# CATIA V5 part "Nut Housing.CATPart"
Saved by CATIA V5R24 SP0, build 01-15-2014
Part number: Nut Housing
Bounding box of the stored display mesh (mm): x -15 to 15, y -30 to 30, z -10 to 10
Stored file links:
  C:\Users\minsi\Google 드라이브\CDL_2019\00_CLASS\00_CAD\기말고사\DMU\Nut Housing.CATPart
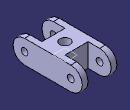
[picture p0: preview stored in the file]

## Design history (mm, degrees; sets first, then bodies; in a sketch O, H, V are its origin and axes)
Body1 (main body)
  Sketch1 on yz-plane, origin (0, 0, 0), H (0, 1, 0), V (0, 0, 1)
    construction line L1 (-20, 0) -> (20, 0)
    point P1 (-20, 0)
    line L2 (-20, 10) -> (20, 10)
    line L3 (20, -10) -> (-20, -10)
    arc A1 centre (20, 0) radius 10 from (20, 10) to (20, -10) cw
    arc A2 centre (-20, 0) radius 10 from (-20, -10) to (-20, 10) cw
    distance L1 L2 = 10
    length L1 = 40
    distance P1 V = 20
    horizontal: L1 H
    tangency: A1 L2, A2 L2, A1 L3, A2 L3
    coincidence: L1 H
  Pad1: profile Sketch1, direction (1, 0, 0), length 15, mirrored extent
  Sketch2 on end face of Pad1, origin (15, 22.454, 0), H (0, 1, 0), V (0, 0, 1)
    point P1 (-2.454, 0)
    reference projected arc E1 centre (-2.454, 0) radius 10 from (-2.454, -10) to (-2.454, 10) ccw from edge [face of Pad1 from Sketch1.A1 | end face of Pad1]
    concentricity: E1 P1
  Hole1: placed by Sketch2, at (15, 20, 0) direction (-1, 0, 0), diameter 6, through (limit type 3)
  Sketch3 on end face of Pad1, origin (15, -24.4239, 1.7761), H (0, 1, 0), V (0, 0, 1)
    point P1 (4.4239, -1.7761)
    reference projected arc E1 centre (4.4239, -1.7761) radius 10 from (4.4239, 8.2239) to (4.4239, -11.7761) ccw from edge [face of Pad1 from Sketch1.A2 | end face of Pad1]
    concentricity: E1 P1
  Hole2: placed by Sketch3, at (15, -20, 0) direction (-1, 0, 0), diameter 6, through (limit type 3)
  Sketch4 on face of Pad1 from Sketch1.L2, origin (-7.6845, 2.0131, 10), H (1, 0, 0), V (0, 1, 0)
    point P1 (7.6845, -2.0131)
    reference intersected line E1 through (0, -2.0131) direction (-1, 0) from zx-plane
    reference intersected line E2 through (7.6845, 0) direction (0, 1) from yz-plane
    coincidence: P1 E1, P1 E2
  Hole3: placed by Sketch4, at (0, 0, 10) direction (0, 0, -1), diameter 9, through (limit type 3)
  Sketch5 on xy-plane, origin (0, 0, 0), H (1, 0, 0), V (0, 1, 0)
    line L1 (-10, 36.9581) -> (-10, 10)
    line L2 (-10, 10) -> (10, 10)
    line L3 (10, 10) -> (10, 36.9581)
    reference projected line E1 (15, 20) -> (15, -20) from edge [face of Pad1 from Sketch1.L2 | end face of Pad1]
    distance L2 H = 10
    distance L3 E1 = 5
    vertical: L1 V, L3 V
    horizontal: L2 H
    symmetry: L1 L3 V
  Pocket1: profile Sketch5, direction (0, 0, -1), through (limit type 3), opposite side through (limit type 3)
  Mirror1: of Pocket1, about zx-plane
